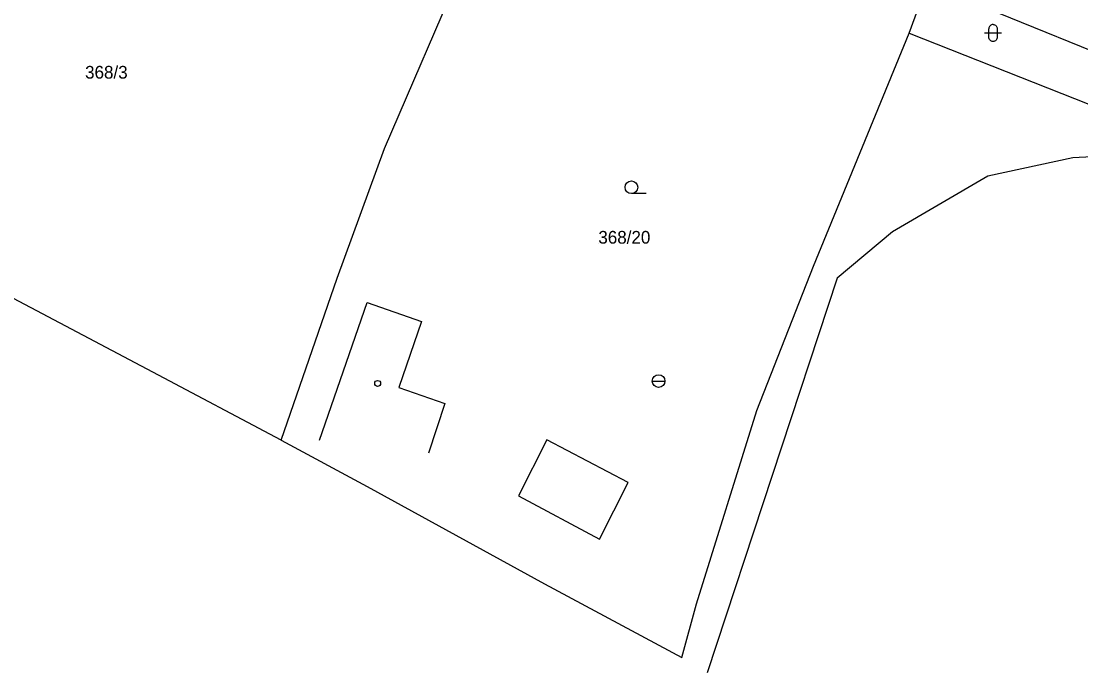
# Model space of a CAD drawing. Extents: x -836568 to -836015, y -1070547 to -1070212.
# Drawn here: x -836423.1 to -836360.6, y -1070448 to -1070409.6 of the extents above; entities that cross this region are included whole.
import ezdxf

# ---------------------------------------------------------------- set-up
doc = ezdxf.new("R2010")
doc.units = 0
for name, color, linetype in [('BodPole_mer', 7, 'Continuous'), ('Budovy_hranice', 7, 'Continuous'), ('Budovy_kody', 7, 'Continuous'), ('Doprava_hranice', 7, 'Continuous'), ('OstPloch_hranice', 7, 'Continuous'), ('OstPloch_kody', 7, 'Continuous'), ('RuianPar_popis', 7, 'Continuous'), ('Stavby_hr_stav', 7, 'Continuous'), ('Stavby_linie', 7, 'Continuous'), ('Vodstvo_body', 7, 'Continuous')]:
    doc.layers.add(name, color=color, linetype=linetype)

msp = doc.modelspace()

# ---------------------------------------------------------------- linework, layer by layer
at = {"layer": 'BodPole_mer'}
for p, q in [((-836370.7, -1070410.27), (-836370.7, -1070410.27)), ((-836401.63, -1070417.07), (-836401.63, -1070417.07)), ((-836361.05, -1070417.62), (-836361.05, -1070417.62)), ((-836366.07, -1070418.7), (-836366.07, -1070418.7)), ((-836371.68, -1070421.97), (-836371.68, -1070421.97)), ((-836376.35, -1070424), (-836376.35, -1070424)), ((-836404.42, -1070424.71), (-836404.42, -1070424.71)), ((-836374.95, -1070424.71), (-836374.95, -1070424.71)), ((-836402.66, -1070426.14), (-836402.66, -1070426.14)), ((-836399.46, -1070427.25), (-836399.46, -1070427.25)), ((-836385.48, -1070430.77), (-836385.48, -1070430.77)), ((-836400.8, -1070431.15), (-836400.8, -1070431.15)), ((-836398.08, -1070432.09), (-836398.08, -1070432.09)), ((-836379.69, -1070432.5), (-836379.69, -1070432.5)), ((-836392.07, -1070434.23), (-836392.07, -1070434.23)), ((-836387.27, -1070436.75), (-836387.27, -1070436.75))]:
    msp.add_line(p, q, dxfattribs=at)
at = {"layer": 'Budovy_hranice'}
for p, q in [((-836405.46, -1070434.26), (-836402.66, -1070426.14)), ((-836402.66, -1070426.14), (-836399.46, -1070427.25)), ((-836399.46, -1070427.25), (-836400.8, -1070431.15)), ((-836400.8, -1070431.15), (-836398.08, -1070432.09)), ((-836398.08, -1070432.09), (-836399.05, -1070435.03))]:
    msp.add_line(p, q, dxfattribs=at)
at = {"layer": 'Budovy_kody'}
msp.add_circle((-836402.04, -1070430.91), 0.175, dxfattribs=at)
at = {"layer": 'Doprava_hranice'}
for points in [[(-836354.29, -1070413.6), (-836369.6, -1070407.37), (-836381.91, -1070402.37), (-836385.59, -1070400.85), (-836388.36, -1070399.67), (-836391.13, -1070398.46), (-836393.85, -1070397.22), (-836395.73, -1070396.35), (-836398.41, -1070395.08), (-836401.16, -1070393.77), (-836403.85, -1070392.4), (-836406.54, -1070391.05), (-836409.24, -1070389.65), (-836411.89, -1070388.24), (-836414.55, -1070386.78), (-836417.54, -1070385.1), (-836418.59, -1070387.07)], [(-836370.7, -1070410.27), (-836360.12, -1070414.44), (-836352.3, -1070417.49), (-836345.8, -1070420.64)]]:
    msp.add_lwpolyline(points, dxfattribs=at)
at = {"layer": 'OstPloch_hranice'}
msp.add_lwpolyline([(-836345.8, -1070420.64), (-836355.7, -1070417.34), (-836361.05, -1070417.62), (-836366.07, -1070418.7), (-836371.68, -1070421.97), (-836374.95, -1070424.71), (-836382.62, -1070447.97)], dxfattribs=at)
at = {"layer": 'OstPloch_kody'}
for p, q in [((-836366.01, -1070410.5), (-836366.01, -1070410)), ((-836365.51, -1070410), (-836365.51, -1070410.5)), ((-836366.26, -1070410.25), (-836365.26, -1070410.25)), ((-836386.205, -1070419.72), (-836387.08, -1070419.72))]:
    msp.add_line(p, q, dxfattribs=at)
for points in [[(-836365.76, -1070409.75), (-836365.805, -1070409.754), (-836365.852, -1070409.768), (-836365.897, -1070409.791), (-836365.937, -1070409.823), (-836365.969, -1070409.863), (-836365.992, -1070409.908), (-836366.006, -1070409.955), (-836366.01, -1070410)], [(-836365.76, -1070409.75), (-836365.715, -1070409.754), (-836365.668, -1070409.768), (-836365.623, -1070409.791), (-836365.583, -1070409.823), (-836365.551, -1070409.863), (-836365.528, -1070409.908), (-836365.514, -1070409.955), (-836365.51, -1070410)], [(-836365.76, -1070410.75), (-836365.805, -1070410.746), (-836365.852, -1070410.732), (-836365.897, -1070410.709), (-836365.937, -1070410.677), (-836365.969, -1070410.637), (-836365.992, -1070410.592), (-836366.006, -1070410.545), (-836366.01, -1070410.5)], [(-836365.51, -1070410.5), (-836365.514, -1070410.545), (-836365.528, -1070410.592), (-836365.551, -1070410.637), (-836365.583, -1070410.677), (-836365.623, -1070410.709), (-836365.668, -1070410.732), (-836365.715, -1070410.746), (-836365.76, -1070410.75)]]:
    msp.add_lwpolyline(points, dxfattribs=at)
msp.add_ellipse((-836387.08, -1070419.345), major_axis=(0.375, 0), ratio=0.999999, dxfattribs=at)
at = {"layer": 'RuianPar_popis'}
for p, q in [((-836419.29, -1070412.94), (-836419.29, -1070412.94)), ((-836389.03, -1070422.67), (-836389.03, -1070422.67))]:
    msp.add_line(p, q, dxfattribs=at)
at = {"layer": 'Stavby_hr_stav'}
msp.add_lwpolyline([(-836387.27, -1070436.75), (-836392.07, -1070434.23), (-836393.73, -1070437.54), (-836388.97, -1070440.09), (-836387.27, -1070436.75)], dxfattribs=at)
at = {"layer": 'Stavby_linie'}
for points in [[(-836407.72, -1070434.26), (-836404.42, -1070424.71), (-836401.63, -1070417.07), (-836396.94, -1070406.16), (-836393.4, -1070397.9)], [(-836407.72, -1070434.26), (-836402.65, -1070436.98), (-836392.21, -1070442.72), (-836384.11, -1070447.06), (-836383.25, -1070443.91), (-836379.69, -1070432.5), (-836376.35, -1070424), (-836370.7, -1070410.27), (-836369.71, -1070407.51)], [(-836407.72, -1070434.26), (-836415.3, -1070430.25), (-836428, -1070423.55), (-836445.87, -1070414.08), (-836449.39, -1070412.25)]]:
    msp.add_lwpolyline(points, dxfattribs=at)
at = {"layer": 'Vodstvo_body'}
msp.add_line((-836385.855, -1070430.77), (-836385.105, -1070430.77), dxfattribs=at)
msp.add_circle((-836385.48, -1070430.77), 0.375, dxfattribs=at)

# ---------------------------------------------------------------- texts
at = {"layer": 'RuianPar_popis'}
for s, p in [('368/3', (-836419.29, -1070412.94)), ('368/20', (-836389.03, -1070422.67))]:
    msp.add_text(s, height=0.75, dxfattribs=at).set_placement(p)

doc.saveas('drawing.dxf')
